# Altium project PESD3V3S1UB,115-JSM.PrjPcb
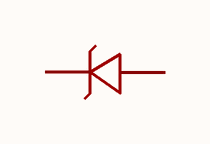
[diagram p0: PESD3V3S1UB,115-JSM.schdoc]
1 sheet, 1 parts. Net scope: global (net labels, ports and power ports of the same name join across sheets).

## Sheet PESD3V3S1UB,115-JSM.schdoc
size 127 x 101 mm

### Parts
D?  pesd3v3s1ub,115-jsm  [SOD-523_L1.2-W0.8-LS1.6-RD]  (value not drawn)

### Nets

Not connected (* = marked no-connect by the designer): D? 1(C) 2(A)

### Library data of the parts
D? = pesd3v3s1ub,115-jsm: 极性:单向;反向截止电压(Vrwm):3.3V;钳位电压:14V;峰值脉冲电流(Ipp):-;峰值脉冲功率(Ppp):-;击穿电压(VBR):5V;; Manufacturer: JSMSEMI(杰盛微); AddInBom: yes; ModelId: 8f56a03db567494d8f4c9d12aa52a741; ModelName: SOD-523_L1.2-W0.8-H0.7-LS1.6; ModelTransform: 62.992,31.496,0,180,0,0,0,0,0; Polarity: 单向; Reverse Stand-Off Voltage (Vrwm): 3.3V; Clamping Voltage: 14V; Voltage - Breakdown: 5V; Reverse Leakage Current (Ir): 900nA; Number of Channels: 单路; level of protection: IEC 61000-4-2; Type: ESD; Junction Capacitance: 105pF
